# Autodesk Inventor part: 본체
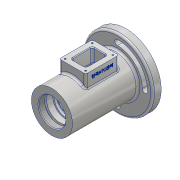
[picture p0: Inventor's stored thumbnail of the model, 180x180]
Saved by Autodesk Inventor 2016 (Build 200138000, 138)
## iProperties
Created: 2017-05
Part Number: 본체
Material: 알루미늄 6061
Document SubType Name: Modeling
Designer: KSEW
Density: 2.7 g/cm^3
Appearance: 알루미늄 - 평지
Mass: 717.463 g
Surface Area: 630.64 cm^2
Volume: 265.727 cm^3
Author: KSEW
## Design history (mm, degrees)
sketch "스케치1"
  geometry: C1 r 31 at (0, 0); 1 further point
  constraints: 1 centre point, 1 coincident
  dimensions: "d0" = 62 diameter of C1
extrude "돌출1" new body sketch "스케치1" stored distance "d1" = 115; taper "d2" = 0 deg
node "작업 평면1"
sketch "스케치2"
  geometry: L1 (-78.678, -1.5)-(78.004, -1.5); L2 (-31, -57.5)-(31, -57.5) reference; L3 (20, 23.5)-(-20, 23.5); L4 (-20, 23.5)-(-20, -26.5); L5 (-20, -26.5)-(20, -26.5); L6 (20, -26.5)-(20, 23.5); L7 (20, 23.5)-(-20, -26.5); L8 (-20, 23.5)-(20, -26.5); 2 further points
  constraints: 14 end point, 2 horizontal, 2 midpoint, 2 parallel, 1 perpendicular, 1 point on line
  dimensions: "d4" = 56 distance between parallel lines of L1 L2; "d5" = 50 distance of L3.end L4.end; "d6" = 40 distance of L3.start L3.end
extrude "돌출2" join sketch "스케치2" stored distance "d7" = 115; taper "d8" = 0 deg
node "작업 평면2"
sketch "스케치3"
  geometry: C1 r 53 at (0, 0); C2 r 31 at (0, 0) reference; 1 further point
  constraints: 1 centre point, 1 coincident
  dimensions: "d10" = 106 diameter of C1
extrude "돌출3" join sketch "스케치3" distance "d11" = 13; taper "d12" = 0 deg
sketch "스케치4"
  geometry: C1 r 53 at (0, 0) reference; A1 r 4 centre (0, 41.5) between (0, 37.5) and (0, 45.5); A2 r 4 centre (-41.5, 0) between (-45.5, 0) and (-37.5, 0); A3 r 4 centre (0, -41.5) between (0, -37.5) and (0, -45.5); A4 r 4 centre (41.5, 0) between (45.5, 0) and (37.5, 0); A5 r 37.5 centre (0, 0) between (0, -37.5) and (37.5, 0); A6 r 37.5 centre (0, 0) between (0, 37.5) and (-37.5, 0); A7 r 45.5 centre (0, 0) between (0, -45.5) and (45.5, 0); A8 r 45.5 centre (0, 0) between (0, 45.5) and (-45.5, 0)
  constraints: 16 point on circle, 8 centre point, 3 equal radius, 2 coincident
  dimensions: "d16" = 8 diameter of A4
extrude "돌출4" cut sketch "스케치4" stored distance "d17" = 50; taper "d18" = 0 deg
sketch "스케치5"
  geometry: L1 (20, 23.5)-(-20, 23.5) reference; L2 (-20, 23.5)-(-20, -26.5) reference; L3 (-20, -26.5)-(20, -26.5) reference; L4 (20, -26.5)-(20, 23.5) reference; L5 (-11, -17.5)-(-11, 14.5); L6 (-11, 14.5)-(11, 14.5); L7 (11, 14.5)-(11, -17.5); L8 (11, -17.5)-(-11, -17.5); 1 further point
  constraints: 8 end point, 3 other
  dimensions: "d19" = 32 distance of L6.end L7.end
extrude "돌출5" cut sketch "스케치5" distance "d20" = 50; taper "d21" = 0 deg
sketch "스케치6"
  geometry: C1 r 31 at (0, 0) reference; 1 further point
  constraints: 1 coincident
hole "구멍1" sketch "스케치6" at (0, 0) diameter "d22" = 40.376; stored, may be unused: countersink angle "d26" = 90 deg, drill point angle "d28" = 118 deg; dims "d23" = 8.5, "d24" = 4, "d25" = 2, "d27" = 9
sketch "스케치7"
  geometry: L1 (-48.5, 0)-(-48.5, 24); L2 (-48.5, 24)-(-45.5, 24); L3 (-45.5, 24)-(-45.5, 20); L4 (-45.5, 20)-(-36.5, 20); L5 (-36.5, 20)-(-36.5, 17.5); L6 (-36.5, 17.5)-(-33.25, 17.5); L7 (-33.25, 17.5)-(-33.25, 18.5); L8 (-33.25, 18.5)-(-31.5, 18.5); L9 (-31.5, 18.5)-(-31.5, 17.5); L10 (-57.5, 31)-(-57.5, -31) reference; L11 (57.5, -31)-(57.5, 31) reference; L12 (57.5, 22)-(45.318, 16.779); L13 (43.5, 14.022)-(43.5, 13.5); L14 (42.5, 12.5)-(36.5, 12.5); L15 (36.2, 12.2)-(36.2, 10); L16 (36.2, 10)-(33.5, 10); L17 (28.5, 16.5)-(30.5, 16.5); L18 (33.5, 13.5)-(33.5, 10); L19 (28.5, 17.2)-(28.5, 16.5); L20 (-1.5, 88.119)-(-1.5, -70.588); L21 (-20.5, 23)-(-20.5, 18.5); L22 (17.5, 23)-(17.5, 18.5); L23 (-17.5, 26)-(14.5, 26); L24 (-31.5, 17.5)-(-21.5, 17.5); L25 (18.5, 17.5)-(28.2, 17.5); L26 (-21.5, 17.5)-(-20.5, 18.5); L27 (18.5, 17.5)-(17.5, 18.5); L28 (42.5, 12.5)-(43.5, 13.5); L29 (57.5, 22)-(57.5, 0); L30 (-48.5, 0)-(57.5, 0); A1 r 0.3 centre (36.5, 12.2) between (36.5, 12.5) and (36.2, 12.2); A2 r 3 centre (-17.5, 23) between (-17.5, 26) and (-20.5, 23); A3 r 3 centre (14.5, 23) between (17.5, 23) and (14.5, 26); A4 r 3 centre (46.5, 14.022) between (45.318, 16.779) and (43.5, 14.022); A5 r 3 centre (30.5, 13.5) between (33.5, 13.5) and (30.5, 16.5); A6 r 0.3 centre (28.2, 17.2) between (28.5, 17.2) and (28.2, 17.5); 9 further points
  constraints: 56 end point, 19 point on line, 12 point on circle, 12 tangent, 11 perpendicular, 6 centre point, 5 vertical, 3 horizontal, 3 parallel, 1 equal radius
  dimensions: "d29" = 9 distance between parallel lines of L1 L10; "d30" = 3 distance of L1.end L2.end; "d31" = 21 distance from line of L5.end L10; "d32" = 26 distance between parallel lines of L10 L9; "d35" = 1.75 distance of L7.end L8.end; "d36" = 60 distance of L9.end point (28.5, 17.5); "d37" = 14 distance from line of L11 point (43.5, 16); "d39" = 2.7 distance of L15.end L16.end; "d40" = 7.3 distance of point (43.5, 12.5) point (36.2, 12.5); "d43" = 0.3 radius of A1; "d51" = 56 distance between parallel lines of L20 L10; "d52" = 38 diameter of L22 L20; "d53" = 38 diameter of L21 L20; "d55" = 3 radius of A2; "d56" = 1 distance of L24.end point (-20.5, 17.5); "d57" = 45 deg angle of L24 L26; "d58" = 1 distance of L25.start point (17.5, 17.5) (= d56); "d59" = 45 deg angle of L25 L27 (= d57); "d60" = 1 distance of L14.start point (43.5, 12.5); "d61" = 45 deg angle of L14 L28; "d62" = 3 radius of A4; "d63" = 3 radius of A5; "d64" = 0.3 radius of A6
revolve "회전1" sketch "스케치7" stored, may be unused: angle "d65" = 90 deg
fillet "모깎기1" dims "d66" = 3
sketch "스케치8"
  geometry: L1 (11, -17.5)-(-11, -17.5) reference; L2 (-11, -17.5)-(-11, 14.5) reference; L3 (-11, 14.5)-(11, 14.5) reference; L4 (11, 14.5)-(11, -17.5) reference; L5 (-15.5, 19)-(-15.5, -22); L6 (-15.5, -22)-(15.5, -22); L7 (15.5, -22)-(15.5, 19); L8 (15.5, 19)-(-15.5, 19); 5 further points
  constraints: 8 end point, 4 coincident, 3 other
  dimensions: "d67" = 41 distance of L5.start L5.end
hole "구멍2" sketch "스케치8" at (-15.5, -22), (15.5, -22), (15.5, 19), (-15.5, 19) diameter "d68" = 2.459; stored, may be unused: countersink angle "d72" = 90 deg, drill point angle "d74" = 118 deg; dims "d69" = 6, "d70" = 4, "d71" = 2, "d73" = 8
fillet "모깎기2" dims "d75" = 3
chamfer "모따기1" distance "d76" = 1; stored, may be unused: second distance "d77" = 2, angle "d78" = 45 deg
fillet "모깎기3" dims "d79" = 3
fillet "모깎기4" dims "d80" = 3
chamfer "모따기2" distance "d81" = 1; stored, may be unused: second distance "d82" = 2, angle "d83" = 45 deg
sketch "스케치9"
  geometry: L1 (0, 0)-(0, 44) reference; L2 (13, -34)-(75, -34) reference; 2 further points
  constraints: 1 other
  dimensions: "d84" = 56 distance from line of point (8, 22) L2; "d85" = 8 distance from line of point (8, 22) L1
feature "엠보싱1" sketch "스케치9" dims "d86" = 0.5, "d87" = 0
fillet "모깎기5" dims "d88" = 3
node "솔리드1"
other parameters: "d3" = 44, "d9" = -3, "d14" = 91, "d41" = 25, "d44" = 32, "d45" = 44, "d46" = 33, "d47" = 35, "d48" = 37, "d50" = 48, "d54" = 52
